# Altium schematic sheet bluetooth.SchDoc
size A4
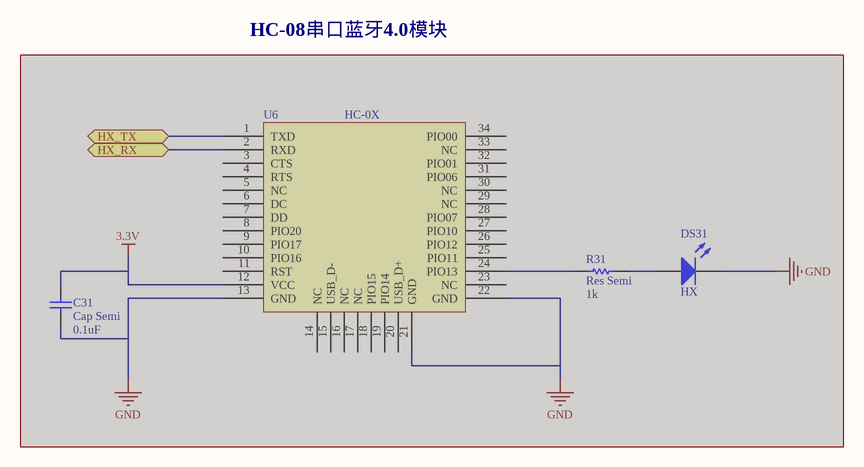
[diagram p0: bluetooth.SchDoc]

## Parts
C31  Cap Semi  value 0.1uF  [C1608-0603]  (masked out: inside a compile mask, not in the netlist)
DS31  HX  [LED0603_AB]  (masked out: inside a compile mask, not in the netlist)
R31  Res Semi  value 1k  [R1608-0603]  (masked out: inside a compile mask, not in the netlist)
U6  HC-0X  [HC-0X_4]  (masked out: inside a compile mask, not in the netlist)

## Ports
HX_RX (bidir), HX_TX (bidir)

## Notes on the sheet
- HC-08串口蓝牙4.0模块

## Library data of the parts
C31 = Cap Semi: Capacitor (Semiconductor SIM Model)
DS31 = LED3: Typical BLUE SiC LED
R31 = Res Semi: Semiconductor Resistor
